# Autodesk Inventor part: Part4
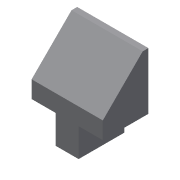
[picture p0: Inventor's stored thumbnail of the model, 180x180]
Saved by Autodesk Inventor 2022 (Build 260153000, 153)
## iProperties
Created: 2002-01
Part Number: Part4
Document SubType Name: Modeling
Designer: ***
Density: 1 g/cm^3
Material: Generic
Appearance: Default
Control State: 0
Master: False
Checked Out: False
Shininess: 77.0
Length Units: 11269
Angle Units: 11279
Time Units: 11290
Mass Units: 11283
Length Display Precision: 3
Angle Display Precision: 2
Density: 0.0
Volumn: 0.0
Area: 0.0
PropertySet Name: Model Information
Author: ***
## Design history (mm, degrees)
sketch "Sketch2"
  geometry: L1 (2.32, -6.969)-(2.32, 13.031); L2 (2.32, 13.031)-(0.32, 13.031); L3 (0.32, 13.031)-(-13.68, -0.969); L4 (-13.68, -0.969)-(-13.68, -6.969); L5 (-13.68, -6.969)-(2.32, -6.969)
  constraints: 10 end point, 2 parallel, 1 perpendicular, 1 vertical
  dimensions: "d0" = 2 distance of L1.end L2.end; "d1" = 135 deg angle of L4 L3; "d2" = 20 distance of L1.start L1.end; "d3" = 16 distance of L4.end L1.start
extrude "Extrusion1" new body sketch "Sketch2" stored distance "d4" = 25; taper "d5" = 0 deg
sketch "Sketch3"
  geometry: L1 (-13.68, -6.969)-(2.32, -6.969); L2 (2.32, -6.969)-(2.32, -16.969); L3 (2.32, -16.969)-(-13.68, -16.969); L4 (-13.68, -16.969)-(-13.68, -6.969); L5 (-13.68, -6.969)-(2.32, -6.969) reference; L6 (-13.68, -0.969)-(-13.68, -6.969) reference; L7 (2.32, -6.969)-(2.32, 13.031) reference
  constraints: 8 end point, 3 collinear, 2 parallel, 1 horizontal, 1 perpendicular
  dimensions: "d6" = 10 distance of L3.end L1.start
extrude "Extrusion2" join sketch "Sketch3" stored distance "d7" = 8; taper "d8" = 0 deg
body "Solid1"
